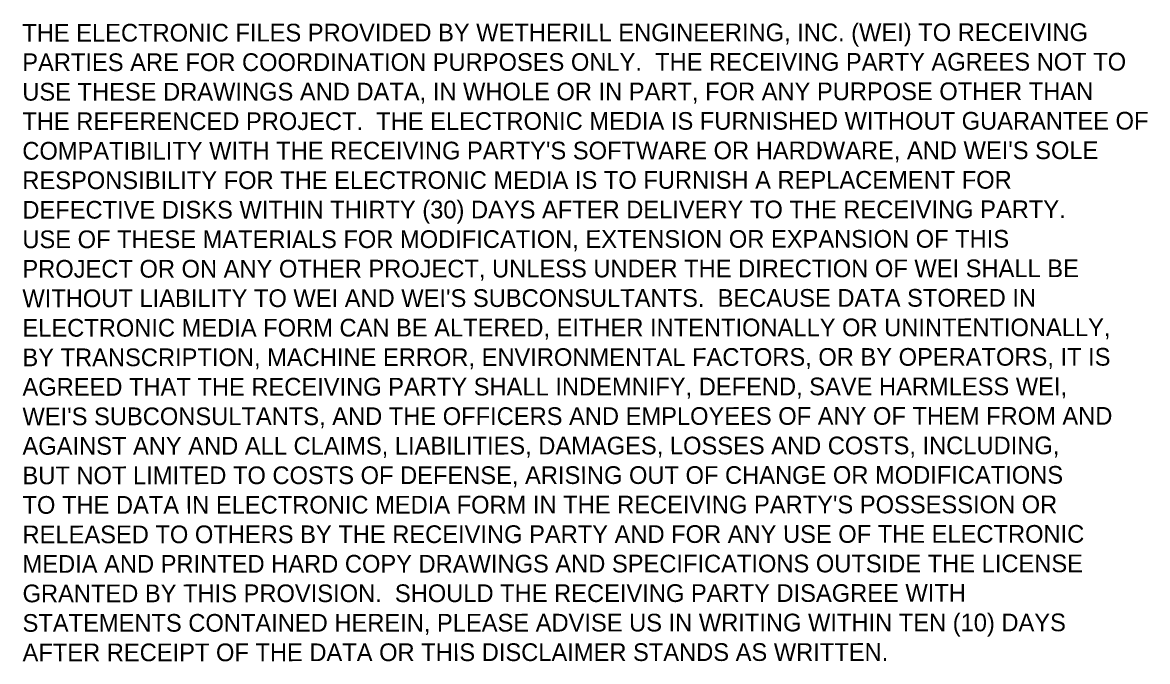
# Model space of a CAD drawing. Extents: x -14026 to 1303, y -10 to 9533.
# Drawn here: x -14026 to -13521, y 2252 to 2539 of the extents above; entities that cross this region are included whole.
import ezdxf

# ---------------------------------------------------------------- set-up
doc = ezdxf.new("R2010")
doc.units = 0
doc.layers.add('Default', color=7, linetype='Continuous')

msp = doc.modelspace()

# ---------------------------------------------------------------- texts
at = {"layer": 'Default'}
for s, p in [('THE ELECTRONIC FILES PROVIDED BY WETHERILL ENGINEERING, INC. (WEI) TO RECEIVING ', (-14026.43, 2530.48)), ('PARTIES ARE FOR COORDINATION PURPOSES ONLY.  THE RECEIVING PARTY AGREES NOT TO ', (-14026.43, 2517.22)), ('USE THESE DRAWINGS AND DATA, IN WHOLE OR IN PART, FOR ANY PURPOSE OTHER THAN ', (-14026.42, 2503.96)), ('THE REFERENCED PROJECT.  THE ELECTRONIC MEDIA IS FURNISHED WITHOUT GUARANTEE OF ', (-14026.41, 2490.7)), ("COMPATIBILITY WITH THE RECEIVING PARTY'S SOFTWARE OR HARDWARE, AND WEI'S SOLE ", (-14026.41, 2477.44)), ('RESPONSIBILITY FOR THE ELECTRONIC MEDIA IS TO FURNISH A REPLACEMENT FOR ', (-14026.4, 2464.18)), ('DEFECTIVE DISKS WITHIN THIRTY (30) DAYS AFTER DELIVERY TO THE RECEIVING PARTY.  ', (-14026.39, 2450.92)), ('USE OF THESE MATERIALS FOR MODIFICATION, EXTENSION OR EXPANSION OF THIS ', (-14026.39, 2437.66)), ('PROJECT OR ON ANY OTHER PROJECT, UNLESS UNDER THE DIRECTION OF WEI SHALL BE ', (-14026.38, 2424.4)), ("WITHOUT LIABILITY TO WEI AND WEI'S SUBCONSULTANTS.  BECAUSE DATA STORED IN ", (-14026.37, 2411.14)), ('ELECTRONIC MEDIA FORM CAN BE ALTERED, EITHER INTENTIONALLY OR UNINTENTIONALLY, ', (-14026.36, 2397.88)), ('BY TRANSCRIPTION, MACHINE ERROR, ENVIRONMENTAL FACTORS, OR BY OPERATORS, IT IS ', (-14026.36, 2384.61)), ('AGREED THAT THE RECEIVING PARTY SHALL INDEMNIFY, DEFEND, SAVE HARMLESS WEI, ', (-14026.35, 2371.35)), ("WEI'S SUBCONSULTANTS, AND THE OFFICERS AND EMPLOYEES OF ANY OF THEM FROM AND ", (-14026.34, 2358.09)), ('AGAINST ANY AND ALL CLAIMS, LIABILITIES, DAMAGES, LOSSES AND COSTS, INCLUDING, ', (-14026.34, 2344.83)), ('BUT NOT LIMITED TO COSTS OF DEFENSE, ARISING OUT OF CHANGE OR MODIFICATIONS ', (-14026.33, 2331.57)), ("TO THE DATA IN ELECTRONIC MEDIA FORM IN THE RECEIVING PARTY'S POSSESSION OR ", (-14026.32, 2318.31)), ('RELEASED TO OTHERS BY THE RECEIVING PARTY AND FOR ANY USE OF THE ELECTRONIC ', (-14026.32, 2305.05)), ('MEDIA AND PRINTED HARD COPY DRAWINGS AND SPECIFICATIONS OUTSIDE THE LICENSE ', (-14026.31, 2291.79)), ('GRANTED BY THIS PROVISION.  SHOULD THE RECEIVING PARTY DISAGREE WITH ', (-14026.3, 2278.53)), ('STATEMENTS CONTAINED HEREIN, PLEASE ADVISE US IN WRITING WITHIN TEN (10) DAYS ', (-14026.3, 2265.27)), ('AFTER RECEIPT OF THE DATA OR THIS DISCLAIMER STANDS AS WRITTEN.', (-14026.29, 2252.01))]:
    msp.add_text(s, height=7.9565, rotation=0.0298, dxfattribs=at).set_placement(p)

doc.saveas('drawing.dxf')
